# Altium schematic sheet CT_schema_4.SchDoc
size 283 x 147 mm
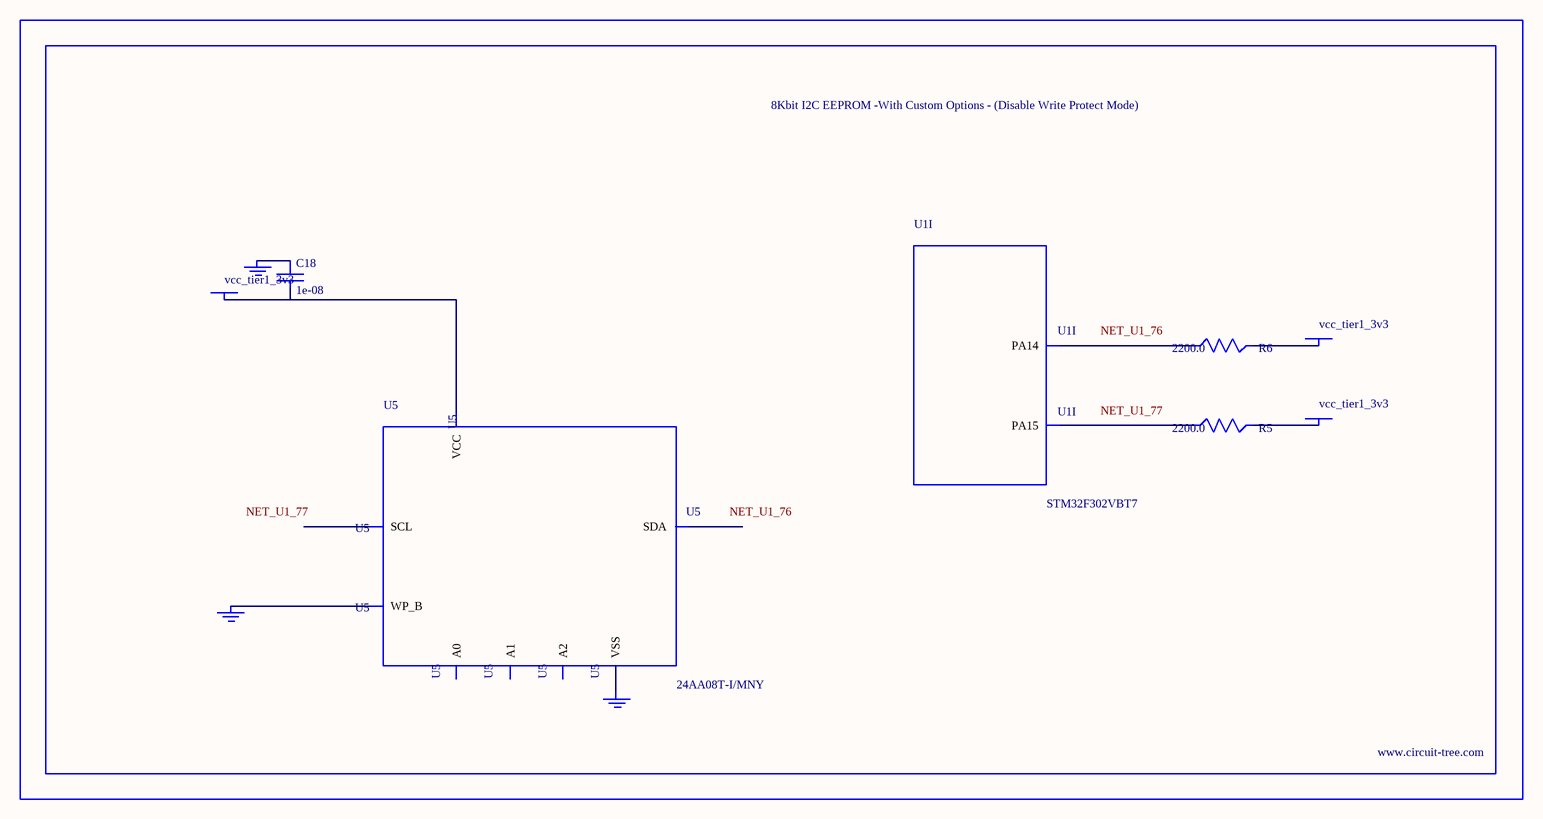
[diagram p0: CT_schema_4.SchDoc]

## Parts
BORDER3  (no value)
C18  1e-08  [C0402]
GND_INSTANCE_3_0  (no value)
GND_INSTANCE_3_1  (no value)
GND_INSTANCE_3_2  (no value)
POWER_INSTANCE_3_0  vcc_tier1_3v3
POWER_INSTANCE_3_1  vcc_tier1_3v3
POWER_INSTANCE_3_2  vcc_tier1_3v3
R5  2200.0  [R0603]
R6  2200.0  [R0603]
U1  STM32F302VBT7  [LQFP100]  (part I of 11)
U5  24AA08T-I/MNY  [TDFN-8/6MM]

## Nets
NetC18_1: C18.1 GND_INSTANCE_3_1.0(GND)
NetC18_2: C18.2 POWER_INSTANCE_3_0.0(PWR) U5.8(VCC)
NetGND_INSTANCE_3_0_0: GND_INSTANCE_3_0.0(GND) U5.7(WP_B)
NetGND_INSTANCE_3_2_0: GND_INSTANCE_3_2.0(GND) U5.4(VSS)
NetPOWER_INSTANCE_3_1_0: POWER_INSTANCE_3_1.0(PWR) R6.2
NetPOWER_INSTANCE_3_2_0: POWER_INSTANCE_3_2.0(PWR) R5.2
NetR5_1: R5.1 U1.77(PA15)
NetR6_1: R6.1 U1.76(PA14)

Not connected (* = marked no-connect by the designer): U5 1(A0) 2(A1) 3(A2) 5(SDA) 6(SCL)

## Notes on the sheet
- Labels drawn without touching a wire or pin: NET_U1_76, NET_U1_77

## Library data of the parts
BORDER3 = BORDER_PAGE3
C18 = C0402C103K3RAC
GND_INSTANCE_3_0-GND_INSTANCE_3_2 = GND
POWER_INSTANCE_3_0-POWER_INSTANCE_3_2 = PWR
R5 R6 = RC0603JR-072K2L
